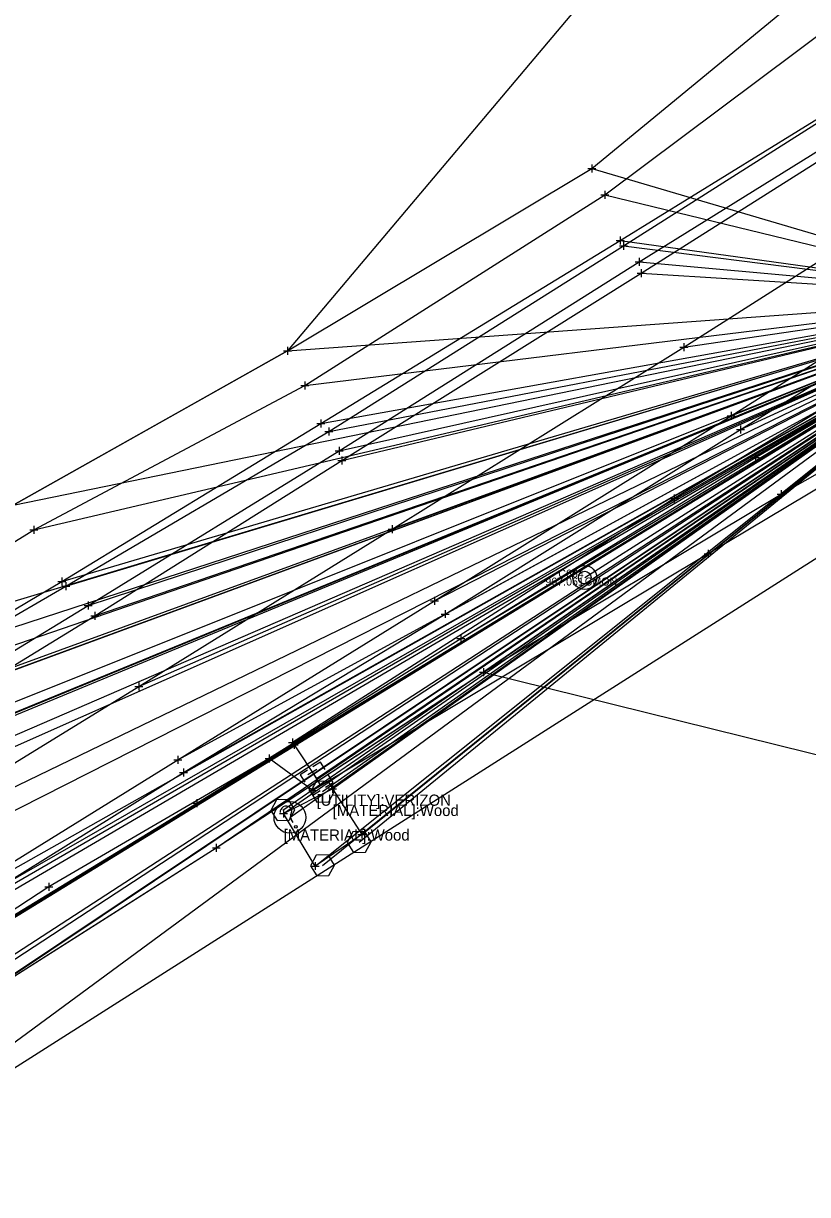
# Model space of a CAD drawing. Extents: x 2048206 to 2051708, y 354200 to 357644.
# Drawn here: x 2049431.6 to 2049529.9, y 356238.7 to 356385.6 of the extents above; entities that cross this region are included whole.
import ezdxf

# ---------------------------------------------------------------- set-up
doc = ezdxf.new("R2010")
doc.units = 0
for name, color, linetype in [('_CIVIL_CONSTRUCTION', 7, 'Continuous'), ('HY_X_Water_Edge', 7, 'Continuous'), ('PM_X_CL_Double_Solid', 7, 'Continuous'), ('PM_X_Edge_Line', 7, 'Continuous'), ('RD_X_Concrete_Pad', 7, 'Continuous'), ('RD_X_GR_Lt', 7, 'Continuous'), ('RW_X_CL_1000_Bearings', 7, 'Continuous'), ('RW_X_CL_1000_Cardinal_Points', 7, 'Continuous'), ('RW_X_CL_1000_Curve_Data', 7, 'Continuous'), ('RW_X_CL_1000_Distances', 7, 'Continuous'), ('RW_X_CL_1000_Stations', 7, 'Continuous'), ('RW_X_CL_100_Bearings', 7, 'Continuous'), ('RW_X_CL_100_Distances', 7, 'Continuous'), ('RW_X_CL_500_Bearings', 7, 'Continuous'), ('RW_X_CL_500_Cardinal_Points', 7, 'Continuous'), ('RW_X_CL_500_Curve_Data', 7, 'Continuous'), ('SC_Scratch1', 7, 'Continuous'), ('SV_P_Control_Cells_Set', 7, 'Continuous'), ('SV_P_Mon_Cells_Set', 7, 'Continuous'), ('SV_X_Terrain_Boundary', 7, 'Continuous'), ('SV_X_Text', 7, 'Continuous'), ('UT_X_Cable_TV', 7, 'Continuous'), ('UT_X_Telecom', 7, 'Continuous')]:
    doc.layers.add(name, color=color, linetype=linetype)

msp = doc.modelspace()

# ---------------------------------------------------------------- linework, layer by layer
at = {"layer": 'HY_X_Water_Edge'}
msp.add_lwpolyline([(2049360.15, 356283.5), (2049391.53, 356301.48), (2049430.27, 356325.21), (2049464.67, 356344.58), (2049502.83, 356367.46), (2049531.12, 356390.8), (2049551.29, 356415), (2049587.36, 356438.21)], dxfattribs=at)
at = {"layer": 'PM_X_CL_Double_Solid'}
msp.add_lwpolyline([(2049375.85, 356259.2), (2049407.64, 356278.84), (2049446.04, 356302.47), (2049477.81, 356322.2), (2049514.36, 356345.05), (2049555.57, 356371.24), (2049580.57, 356387.08), (2049597.36, 356397.99), (2049622.58, 356414.43), (2049657.71, 356438.71), (2049689.55, 356461.77), (2049716.26, 356482.53), (2049748.26, 356508.44), (2049787.5, 356543.51), (2049807.89, 356562.69), (2049832.63, 356587.13)], dxfattribs=at)
at = {"layer": 'PM_X_Edge_Line'}
for points in [[(2049370.29, 356268.21), (2049401.1, 356287.18), (2049440.53, 356311.34), (2049471.49, 356330.83), (2049508.99, 356354.34), (2049549.13, 356379.71), (2049574.88, 356396.03), (2049597.51, 356410.76), (2049600.43, 356412.78), (2049602.51, 356414.08), (2049606.07, 356416.36), (2049609.95, 356418.83), (2049616.41, 356423.19), (2049651.04, 356446.85), (2049683, 356470.3), (2049709.5, 356490.86), (2049741.12, 356516.75), (2049780.37, 356551.36), (2049801.22, 356570.77), (2049825.54, 356594.9)], [(2049381.31, 356250.14), (2049413.48, 356270.07), (2049450.91, 356293.28), (2049483.11, 356313.23), (2049520.27, 356336.44), (2049560.54, 356361.97), (2049585.44, 356377.69), (2049604.83, 356390.29), (2049628.89, 356406.09), (2049663.97, 356430.06), (2049696.02, 356453.42), (2049722.97, 356474.28), (2049754.43, 356500.26), (2049794.54, 356535.57), (2049814.95, 356554.55), (2049840.5, 356579.69)]]:
    msp.add_lwpolyline(points, dxfattribs=at)
at = {"layer": 'RD_X_Concrete_Pad'}
msp.add_lwpolyline([(2049470.33, 356289.63), (2049473.98, 356283.93), (2049468.14, 356279.96), (2049464.17, 356286.55)], close=True, dxfattribs=at)
at = {"layer": 'RD_X_GR_Lt'}
msp.add_lwpolyline([(2049366.77, 356272.94), (2049397.1, 356292.33), (2049436.39, 356315.64), (2049468.85, 356335.46), (2049506.36, 356358.42), (2049546.62, 356383.24), (2049572.79, 356399.73), (2049597.57, 356415.65), (2049605.8, 356420.98), (2049614.6, 356426.92), (2049627.17, 356435.72), (2049647.48, 356452.34)], dxfattribs=at)
at = {"layer": 'RW_X_CL_1000_Bearings'}
msp.add_line((2049557.32, 356351.32), (2049248.99, 356162.95), dxfattribs=at)
msp.add_line((2049557.32, 356351.32), (2049248.99, 356162.95), dxfattribs=at)
at = {"layer": 'RW_X_CL_1000_Cardinal_Points'}
for p in [(2049502.83, 356367.46), (2049504.44, 356364.13), (2049506.36, 356358.42), (2049506.78, 356357.74), (2049508.77, 356355.76), (2049508.99, 356354.34), (2049173.02, 356101.71), (2049173.02, 356101.71), (2049249.01, 356162.97), (2049249.02, 356162.97), (2049360.15, 356283.5), (2049363.17, 356280.43), (2049366.77, 356272.94), (2049367.04, 356272.65), (2049369.24, 356269.8), (2049370.29, 356268.21), (2049375.85, 356259.2), (2049375.85, 356259.2), (2049381.31, 356250.14), (2049382.2, 356248.75), (2049384.67, 356245.45), (2049387.25, 356240), (2049391.53, 356301.48), (2049393.86, 356298.02), (2049397.1, 356292.33), (2049398.29, 356234.18), (2049398.29, 356234.18), (2049398.92, 356292.97), (2049399.69, 356288.2), (2049400.57, 356246.41), (2049401.1, 356287.18), (2049407.64, 356278.84), (2049407.64, 356278.84), (2049413.48, 356270.07), (2049414.46, 356268.53), (2049416.71, 356265.21), (2049420.38, 356259.78), (2049430.27, 356325.21), (2049432.87, 356322.14), (2049436.39, 356315.64), (2049436.87, 356315.05), (2049439.67, 356312.64), (2049440.53, 356311.34), (2049446.04, 356302.47), (2049446.04, 356302.47), (2049450.91, 356293.28), (2049451.64, 356291.67), (2049453.29, 356287.83), (2049455.75, 356282.23), (2049464.08, 356286.98), (2049464.17, 356286.55), (2049464.67, 356344.58), (2049464.98, 356286.06), (2049466.85, 356340.25), (2049468.14, 356279.96), (2049468.31, 356290.92), (2049468.85, 356335.46), (2049469.05, 356289.3), (2049469.07, 356280.03), (2049469.85, 356334.46), (2049470.33, 356289.63), (2049471.15, 356332.04), (2049471.49, 356330.83), (2049473.64, 356282.96), (2049473.98, 356283.93), (2049477.81, 356322.2), (2049477.81, 356322.2), (2049483.11, 356313.23), (2049484.42, 356311.57), (2049486.41, 356308.51), (2049489.23, 356304.28), (2049501.93, 356316.14), (2049514.36, 356345.05), (2049514.36, 356345.05), (2049520.27, 356336.44), (2049521.46, 356334.72), (2049523.32, 356331.21), (2049526.57, 356326.62)]:
    msp.add_line(p, (2049557.32, 356351.32), dxfattribs=at)
at = {"layer": 'RW_X_CL_1000_Curve_Data'}
for points in [[(2049363.17, 356280.43), (2049393.86, 356298.02), (2049432.87, 356322.14), (2049466.85, 356340.25), (2049504.44, 356364.13), (2049533.43, 356385.85), (2049569.2, 356408.58), (2049590.57, 356419.09), (2049594.09, 356418.77), (2049596.65, 356417.46), (2049597.66, 356416.37), (2049599.02, 356414.8)], [(2049387.25, 356240), (2049420.38, 356259.78), (2049455.75, 356282.23), (2049489.23, 356304.28), (2049526.57, 356326.62), (2049567.42, 356349.88), (2049592.62, 356365.75), (2049607.16, 356377.43), (2049609.52, 356380.2), (2049609.93, 356383.07)]]:
    msp.add_lwpolyline(points, dxfattribs=at)
at = {"layer": 'RW_X_CL_1000_Distances'}
msp.add_lwpolyline([(2049375.85, 356259.2), (2049407.64, 356278.84), (2049446.04, 356302.47), (2049477.81, 356322.2), (2049514.36, 356345.05), (2049555.57, 356371.24), (2049580.57, 356387.08), (2049597.36, 356397.99), (2049622.58, 356414.43), (2049657.71, 356438.71), (2049689.55, 356461.77), (2049716.26, 356482.53), (2049748.26, 356508.44), (2049787.5, 356543.51), (2049807.89, 356562.69), (2049832.63, 356587.13)], dxfattribs=at)
at = {"layer": 'RW_X_CL_1000_Stations'}
for points in [[(2049384.67, 356245.45), (2049416.71, 356265.21), (2049453.29, 356287.83), (2049486.41, 356308.51), (2049523.32, 356331.21), (2049564.11, 356356.23), (2049589.23, 356371.82), (2049607.23, 356384.34), (2049608.79, 356386.35), (2049611.22, 356388.3), (2049614.01, 356389.53), (2049617.63, 356390.26), (2049633.05, 356400.32), (2049668.45, 356424.77), (2049699.83, 356447.65), (2049728.19, 356468.27), (2049758.22, 356495.14), (2049799.22, 356531.65), (2049818.68, 356550.01), (2049844.65, 356575.39)], [(2049367.04, 356272.65), (2049398.92, 356292.97), (2049436.87, 356315.05), (2049469.85, 356334.46), (2049506.78, 356357.74), (2049546.65, 356383.05), (2049572.86, 356399.66), (2049597.78, 356415.49)]]:
    msp.add_lwpolyline(points, dxfattribs=at)
at = {"layer": 'RW_X_CL_100_Bearings'}
for radius in [1.5, 0.8]:
    msp.add_circle((2049501.93, 356316.14), radius, dxfattribs=at)
at = {"layer": 'RW_X_CL_100_Distances'}
for points in [[(2049369.24, 356269.8), (2049399.69, 356288.2), (2049439.67, 356312.64), (2049471.15, 356332.04), (2049508.77, 356355.76), (2049548.41, 356380.39), (2049574.36, 356397.56), (2049598.93, 356414.15), (2049600.34, 356415.6), (2049602.48, 356416.72), (2049605.55, 356417.98), (2049609.34, 356420.32), (2049615.78, 356424.71), (2049650.25, 356448.26), (2049682.16, 356471.57), (2049708.61, 356492.19), (2049740.27, 356518.46), (2049779.27, 356552.86), (2049799.72, 356572.07), (2049825.1, 356595.26)], [(2049382.2, 356248.75), (2049414.46, 356268.53), (2049451.64, 356291.67), (2049484.42, 356311.57), (2049521.46, 356334.72), (2049562.27, 356359.86), (2049586.57, 356375.27), (2049606.37, 356387.97), (2049630.26, 356403.8), (2049665.35, 356428.06), (2049697.09, 356451.51), (2049724.33, 356472.6), (2049755.38, 356498.64), (2049795.79, 356534.44), (2049816.11, 356553.32), (2049841.77, 356578.41)]]:
    msp.add_lwpolyline(points, dxfattribs=at)
at = {"layer": 'RW_X_CL_500_Bearings'}
for p, q in [((2049467.23, 356291.43), (2049468.34, 356292.11)), ((2049468.84, 356290.07), (2049467.79, 356291.77)), ((2049468.31, 356290.92), (2049468.31, 356290.92))]:
    msp.add_line(p, q, dxfattribs=at)
for points in [[(2049469.38, 356292.05), (2049468.8, 356292.99), (2049467.86, 356292.41)], [(2049467.18, 356291.98), (2049466.25, 356291.4), (2049466.83, 356290.47)], [(2049469.44, 356289.86), (2049470.38, 356290.44), (2049469.8, 356291.37)], [(2049467.25, 356289.79), (2049467.83, 356288.86), (2049468.76, 356289.44)]]:
    msp.add_lwpolyline(points, dxfattribs=at)
at = {"layer": 'RW_X_CL_500_Cardinal_Points'}
for points in [[(2049468.35, 356287.97), (2049469.84, 356288.02), (2049470.55, 356289.34), (2049469.76, 356290.62), (2049468.26, 356290.57), (2049467.55, 356289.25), (2049468.35, 356287.97)], [(2049463.37, 356285.65), (2049464.87, 356285.7), (2049465.58, 356287.02), (2049464.79, 356288.3), (2049463.29, 356288.25), (2049462.58, 356286.93), (2049463.37, 356285.65)], [(2049472.94, 356281.64), (2049474.44, 356281.69), (2049475.14, 356283.01), (2049474.35, 356284.28), (2049472.85, 356284.24), (2049472.15, 356282.91), (2049472.94, 356281.64)], [(2049468.36, 356278.71), (2049469.86, 356278.76), (2049470.57, 356280.08), (2049469.78, 356281.35), (2049468.28, 356281.31), (2049467.57, 356279.98), (2049468.36, 356278.71)]]:
    msp.add_lwpolyline(points, dxfattribs=at)
at = {"layer": 'RW_X_CL_500_Curve_Data'}
msp.add_line((2049465.38, 356285.42), (2049465.13, 356285.82), dxfattribs=at)
for centre, radius in [((2049464.98, 356286.06), 2), ((2049465.73, 356284.86), 0.17)]:
    msp.add_circle(centre, radius, dxfattribs=at)
for centre, radius, start, end in [((2049464.5, 356286.71), 0.754, 120.1654, 184.3799), ((2049464.51, 356286.8), 0.688, 323.7743, 124.2997), ((2049465.61, 356286.17), 0.587, 157.3031, 215.9243)]:
    msp.add_arc(centre, radius, start, end, dxfattribs=at)
at = {"layer": 'SC_Scratch1'}
for p, q in [((2049502.83, 356367.96), (2049502.83, 356366.96)), ((2049502.33, 356367.46), (2049503.33, 356367.46)), ((2049502.83, 356367.46), (2049502.83, 356367.46)), ((2049504.44, 356364.63), (2049504.44, 356363.63)), ((2049503.94, 356364.13), (2049504.94, 356364.13)), ((2049504.44, 356364.13), (2049504.44, 356364.13)), ((2049506.36, 356358.92), (2049506.36, 356357.92)), ((2049505.86, 356358.42), (2049506.86, 356358.42)), ((2049506.28, 356357.74), (2049507.28, 356357.74)), ((2049506.36, 356358.42), (2049506.36, 356358.42)), ((2049506.78, 356358.24), (2049506.78, 356357.24)), ((2049506.78, 356357.74), (2049506.78, 356357.74)), ((2049508.77, 356356.26), (2049508.77, 356355.26)), ((2049508.27, 356355.76), (2049509.27, 356355.76)), ((2049508.49, 356354.34), (2049509.49, 356354.34)), ((2049508.77, 356355.76), (2049508.77, 356355.76)), ((2049508.99, 356354.84), (2049508.99, 356353.84)), ((2049508.99, 356354.34), (2049508.99, 356354.34)), ((2049514.36, 356345.55), (2049514.36, 356344.55)), ((2049514.36, 356345.55), (2049514.36, 356344.55)), ((2049464.17, 356344.58), (2049465.17, 356344.58)), ((2049464.67, 356345.08), (2049464.67, 356344.08)), ((2049464.67, 356344.58), (2049464.67, 356344.58)), ((2049513.86, 356345.05), (2049514.86, 356345.05)), ((2049513.86, 356345.05), (2049514.86, 356345.05)), ((2049514.36, 356345.05), (2049514.36, 356345.05)), ((2049514.36, 356345.05), (2049514.36, 356345.05)), ((2049466.35, 356340.25), (2049467.35, 356340.25)), ((2049466.85, 356340.75), (2049466.85, 356339.75)), ((2049466.85, 356340.25), (2049466.85, 356340.25)), ((2049520.27, 356336.94), (2049520.27, 356335.94)), ((2049468.35, 356335.46), (2049469.35, 356335.46)), ((2049468.85, 356335.96), (2049468.85, 356334.96)), ((2049468.85, 356335.46), (2049468.85, 356335.46)), ((2049519.77, 356336.44), (2049520.77, 356336.44)), ((2049520.27, 356336.44), (2049520.27, 356336.44)), ((2049469.35, 356334.46), (2049470.35, 356334.46)), ((2049469.85, 356334.96), (2049469.85, 356333.96)), ((2049469.85, 356334.46), (2049469.85, 356334.46)), ((2049520.96, 356334.72), (2049521.96, 356334.72)), ((2049521.46, 356335.22), (2049521.46, 356334.22)), ((2049521.46, 356334.72), (2049521.46, 356334.72)), ((2049471.15, 356332.54), (2049471.15, 356331.54)), ((2049470.65, 356332.04), (2049471.65, 356332.04)), ((2049470.99, 356330.83), (2049471.99, 356330.83)), ((2049471.15, 356332.04), (2049471.15, 356332.04)), ((2049471.49, 356331.33), (2049471.49, 356330.33)), ((2049471.49, 356330.83), (2049471.49, 356330.83)), ((2049522.82, 356331.21), (2049523.82, 356331.21)), ((2049523.32, 356331.71), (2049523.32, 356330.71)), ((2049523.32, 356331.21), (2049523.32, 356331.21)), ((2049513.15, 356326.57), (2049513.15, 356325.57)), ((2049526.07, 356326.62), (2049527.07, 356326.62)), ((2049526.57, 356327.12), (2049526.57, 356326.12)), ((2049526.57, 356326.62), (2049526.57, 356326.62)), ((2049512.65, 356326.07), (2049513.65, 356326.07)), ((2049513.15, 356326.07), (2049513.15, 356326.07)), ((2049432.37, 356322.14), (2049433.37, 356322.14)), ((2049432.87, 356322.64), (2049432.87, 356321.64)), ((2049432.87, 356322.14), (2049432.87, 356322.14)), ((2049477.31, 356322.2), (2049478.31, 356322.2)), ((2049477.31, 356322.2), (2049478.31, 356322.2)), ((2049477.81, 356322.7), (2049477.81, 356321.7)), ((2049477.81, 356322.7), (2049477.81, 356321.7)), ((2049477.81, 356322.2), (2049477.81, 356322.2)), ((2049477.81, 356322.2), (2049477.81, 356322.2)), ((2049516.89, 356319.13), (2049517.89, 356319.13)), ((2049517.39, 356319.63), (2049517.39, 356318.63)), ((2049517.39, 356319.13), (2049517.39, 356319.13)), ((2049436.39, 356316.14), (2049436.39, 356315.14)), ((2049435.89, 356315.64), (2049436.89, 356315.64)), ((2049436.37, 356315.05), (2049437.37, 356315.05)), ((2049436.39, 356315.64), (2049436.39, 356315.64)), ((2049436.87, 356315.55), (2049436.87, 356314.55)), ((2049436.87, 356315.05), (2049436.87, 356315.05)), ((2049482.61, 356313.23), (2049483.61, 356313.23)), ((2049483.11, 356313.73), (2049483.11, 356312.73)), ((2049483.11, 356313.23), (2049483.11, 356313.23)), ((2049439.17, 356312.64), (2049440.17, 356312.64)), ((2049439.67, 356313.14), (2049439.67, 356312.14)), ((2049439.67, 356312.64), (2049439.67, 356312.64)), ((2049440.53, 356311.84), (2049440.53, 356310.84)), ((2049484.42, 356312.07), (2049484.42, 356311.07)), ((2049440.03, 356311.34), (2049441.03, 356311.34)), ((2049440.53, 356311.34), (2049440.53, 356311.34)), ((2049483.92, 356311.57), (2049484.92, 356311.57)), ((2049484.42, 356311.57), (2049484.42, 356311.57)), ((2049486.41, 356309.01), (2049486.41, 356308.01)), ((2049485.91, 356308.51), (2049486.91, 356308.51)), ((2049486.41, 356308.51), (2049486.41, 356308.51)), ((2049489.23, 356304.78), (2049489.23, 356303.78)), ((2049446.04, 356302.97), (2049446.04, 356301.97)), ((2049446.04, 356302.97), (2049446.04, 356301.97)), ((2049488.73, 356304.28), (2049489.73, 356304.28)), ((2049489.23, 356304.28), (2049489.23, 356304.28)), ((2049445.54, 356302.47), (2049446.54, 356302.47)), ((2049445.54, 356302.47), (2049446.54, 356302.47)), ((2049446.04, 356302.47), (2049446.04, 356302.47)), ((2049446.04, 356302.47), (2049446.04, 356302.47)), ((2049465.28, 356295.96), (2049465.28, 356294.96)), ((2049465.49, 356295.67), (2049465.49, 356294.67)), ((2049464.78, 356295.46), (2049465.78, 356295.46)), ((2049464.99, 356295.17), (2049465.99, 356295.17)), ((2049465.28, 356295.46), (2049465.28, 356295.46)), ((2049465.49, 356295.17), (2049465.49, 356295.17)), ((2049450.41, 356293.28), (2049451.41, 356293.28)), ((2049450.91, 356293.78), (2049450.91, 356292.78)), ((2049450.91, 356293.28), (2049450.91, 356293.28)), ((2049461.87, 356293.44), (2049462.87, 356293.44)), ((2049462.37, 356293.94), (2049462.37, 356292.94)), ((2049462.37, 356293.44), (2049462.37, 356293.44)), ((2049451.14, 356291.67), (2049452.14, 356291.67)), ((2049451.64, 356292.17), (2049451.64, 356291.17)), ((2049451.64, 356291.67), (2049451.64, 356291.67)), ((2049467.86, 356289.93), (2049467.86, 356288.93)), ((2049470.33, 356290.13), (2049470.33, 356289.13)), ((2049453.29, 356288.33), (2049453.29, 356287.33)), ((2049467.36, 356289.43), (2049468.36, 356289.43)), ((2049467.86, 356289.43), (2049467.86, 356289.43)), ((2049469.83, 356289.63), (2049470.83, 356289.63)), ((2049470.33, 356289.63), (2049470.33, 356289.63)), ((2049452.79, 356287.83), (2049453.79, 356287.83)), ((2049453.29, 356287.83), (2049453.29, 356287.83)), ((2049464.17, 356287.05), (2049464.17, 356286.05)), ((2049463.67, 356286.55), (2049464.67, 356286.55)), ((2049464.17, 356286.55), (2049464.17, 356286.55)), ((2049473.48, 356283.93), (2049474.48, 356283.93)), ((2049473.98, 356284.43), (2049473.98, 356283.43)), ((2049473.98, 356283.93), (2049473.98, 356283.93)), ((2049455.75, 356282.73), (2049455.75, 356281.73)), ((2049455.25, 356282.23), (2049456.25, 356282.23)), ((2049455.75, 356282.23), (2049455.75, 356282.23)), ((2049467.64, 356279.96), (2049468.64, 356279.96)), ((2049468.14, 356280.46), (2049468.14, 356279.46)), ((2049468.14, 356279.96), (2049468.14, 356279.96)), ((2049434.24, 356277.33), (2049435.24, 356277.33)), ((2049434.74, 356277.83), (2049434.74, 356276.83)), ((2049434.74, 356277.33), (2049434.74, 356277.33))]:
    msp.add_line(p, q, dxfattribs=at)
at = {"layer": 'SV_X_Terrain_Boundary'}
for points in [[(2049732.64, 356530.57), (2049718.52, 356518.61), (2049694.48, 356508.98), (2049649.25, 356512.45), (2049613.86, 356480.86), (2049572.43, 356450.17), (2049562.87, 356442.98), (2049519.66, 356406.66), (2049519.46, 356406.47), (2049501.84, 356388.73), (2049464.67, 356344.58), (2049452.06, 356337.48), (2049430.27, 356325.21), (2049412.85, 356314.54), (2049391.53, 356301.48), (2049381.84, 356295.93), (2049360.15, 356283.5)], [(2049375.85, 356259.2), (2049382.2, 356248.75), (2049384.67, 356245.45), (2049387.25, 356240), (2049408.72, 356252.81), (2049420.38, 356259.78), (2049441.48, 356273.17), (2049455.75, 356282.23), (2049476.63, 356295.98), (2049489.23, 356304.28), (2049538.2, 356292.15)]]:
    msp.add_lwpolyline(points, dxfattribs=at)
at = {"layer": 'UT_X_Cable_TV'}
msp.add_lwpolyline([(2049173.02, 356101.71), (2049398.29, 356234.18), (2049648.28, 356393.26), (2049839.38, 356550.87), (2049967.48, 356704.03)], dxfattribs=at)
at = {"layer": 'UT_X_Telecom'}
for points in [[(2049850.43, 356569.7), (2049830.16, 356550.49), (2049805.94, 356528.04), (2049766.42, 356494.8), (2049727.75, 356461.86), (2049691.42, 356434.05), (2049649.69, 356403.16), (2049608.1, 356376.9), (2049565.89, 356349.66), (2049558.29, 356353.33), (2049513.15, 356326.07), (2049465.28, 356295.46), (2049465.49, 356295.17), (2049468.31, 356290.92)], [(2049852.66, 356568.7), (2049832.09, 356548.43), (2049807.81, 356526.38), (2049768.27, 356493.06), (2049729.69, 356460.16), (2049693.43, 356433.05), (2049650.82, 356402.18), (2049609.75, 356374.99), (2049566.91, 356348.69), (2049517.39, 356319.13), (2049467.86, 356289.43)], [(2049467.86, 356289.43), (2049462.37, 356293.44), (2049434.74, 356277.33), (2049399.5, 356254.22), (2049400.94, 356247.56)]]:
    msp.add_lwpolyline(points, dxfattribs=at)

# ---------------------------------------------------------------- texts
at = {"layer": '_CIVIL_CONSTRUCTION'}
msp.add_text('CMON', height=1, dxfattribs=at).set_placement((2049501.93, 356315.14))
at = {"layer": 'SV_P_Control_Cells_Set'}
msp.add_text('C664', height=1, dxfattribs=at).set_placement((2049498.61, 356316.14))
at = {"layer": 'SV_P_Mon_Cells_Set'}
msp.add_text('967.061', height=1, dxfattribs=at).set_placement((2049496.99, 356315.14))
at = {"layer": 'SV_X_Text'}
for s, p in [('[UTILITY]:VERIZON', (2049468.31, 356287.52)), ('[MATERIAL]:Wood', (2049470.33, 356286.23)), ('[MATERIAL]:Wood', (2049464.17, 356283.15))]:
    msp.add_text(s, height=1.4, dxfattribs=at).set_placement(p)

doc.saveas('drawing.dxf')
